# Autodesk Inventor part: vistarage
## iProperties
Shininess: 21.0
Length Units: 11269
Angle Units: 11279
Time Units: 11290
Mass Units: 11283
Length Display Precision: 3
Angle Display Precision: 2
Compacted: True
Created: 2002-01
Part Number: vistarage
Material: Par défaut
Document SubType Name: Modélisation
Designer: pichon
Density: 0.0
Volumn: 0.0
Area: 0.0
PropertySet Name: Model Information
Control State: 0
Master: False
Checked Out: False
Author: pichon
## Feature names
1. Révolution1 [Revolution]
2. Révolution2 [Revolution]
3. Extrusion1
